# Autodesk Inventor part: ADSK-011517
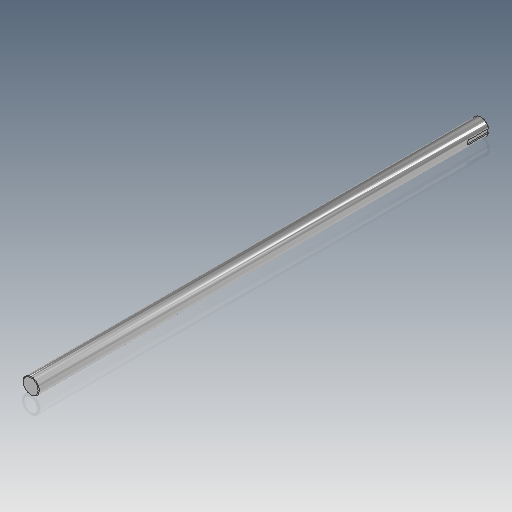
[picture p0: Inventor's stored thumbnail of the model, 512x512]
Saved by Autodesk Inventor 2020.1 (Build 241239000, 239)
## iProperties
Created: 2000-02
Part Number: ADSK-011517
Material: RA HRS
Description: SHFT-T,TH,FX,07,06,236,ACME,RH
Document SubType Name: Modeling
Designer: cmcgourin
Density: 7.83 g/cm^3
Appearance: Chrom - poliert
Mass: 1362.93 g
Surface Area: 355.28 cm^2
Volume: 174.065 cm^3
Control State: 0
Checked Out: False
Master: False
Shininess: 0.0
Length Units: 11269
Angle Units: 11279
Time Units: 11290
Mass Units: 11283
Length Display Precision: 3
Angle Display Precision: 2
Compacted: True
Cutlength: 23.63
Material Desc: THREADED-ROD,0.750-06ACME,RH
Material_Number: A084661
Dimensions: 20x20x555 mm
Mass: 1,363 kg
DocNumber: ADSK-011517.ipt
Folder: 01 - Themengebiete\Simplification\01 - Packaging machine\
VDS_Category: 3D Komponenten
Density: 0.0
Volumn: 0.0
Area: 0.0
PropertySet Name: Model Information
Author: cmcgourin
Revision Number: -
Title: shaft
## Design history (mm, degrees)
node "Extrusion1" dims "d1" = 555, "d2" = 0
  sketch "Sketch1"
    geometry: C1 r 10 at (0, 0); 1 further point
    constraints: 1 centre point, 1 coincident
    dimensions: "d0" = 20 diameter of C1
workplane "Work Plane1"
node "End_mill_straight1"
node "Chamfer1" dims "d15" = 0.79375, "d16" = 0.79375, "d17" = 45 deg
sketch "Skizze3"
  geometry: L1 (9.206, 0)-(-9.206, 0) reference; L2 (-2.5, 0)-(-2.5, 25); L3 (2.5, 25)-(2.5, 0); A1 r 2.5 centre (0, 25) between (2.5, 25) and (-2.5, 25); 2 further points
  constraints: 4 end point, 2 point on circle, 2 point on line, 2 tangent, 1 centre point, 1 midpoint, 1 perpendicular, 1 vertical, 1 vertical alignment
  dimensions: "d18" = 25 distance of L2.start L2.end; "d19" = 2.5 radius of A1
extrude "Extrusion2" cut sketch "Skizze3" distance "d20" = 2; taper "d21" = 0 deg
node "Solide1"
node "Corps solides"
node "Corps surfaciques"
sketch "Sketch2"
  geometry: L1 (-13.275, -49.751)-(12.125, -49.751); L2 (12.125, -44.989)-(-13.275, -44.989); L3 (-13.275, -47.37)-(12.125, -47.37); L4 (-18.649, -37.37)-(-18.649, -57.37) reference; L5 (-18.649, -47.37)-(87.477, -47.37); L6 (-10.1, -56.895)-(-10.1, -37.845) reference; A1 r 2.381 centre (-13.275, -47.37) between (-13.275, -44.989) and (-13.275, -49.751); A2 r 2.381 centre (12.125, -47.37) between (12.125, -49.751) and (12.125, -44.989)
  constraints: 8 end point, 4 point on circle, 4 tangent, 2 centre point, 1 horizontal, 1 midpoint, 1 parallel, 1 perpendicular
  dimensions: "d3" = 2.38125 radius of A2 (derived); "d6" = 0 distance between parallel lines of L5 L3; "d8" = 25.4 distance of L2.start L2.end; "d14" = 3.175 distance from line of L1.start L6
